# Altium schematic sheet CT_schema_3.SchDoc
size 200 x 173 mm
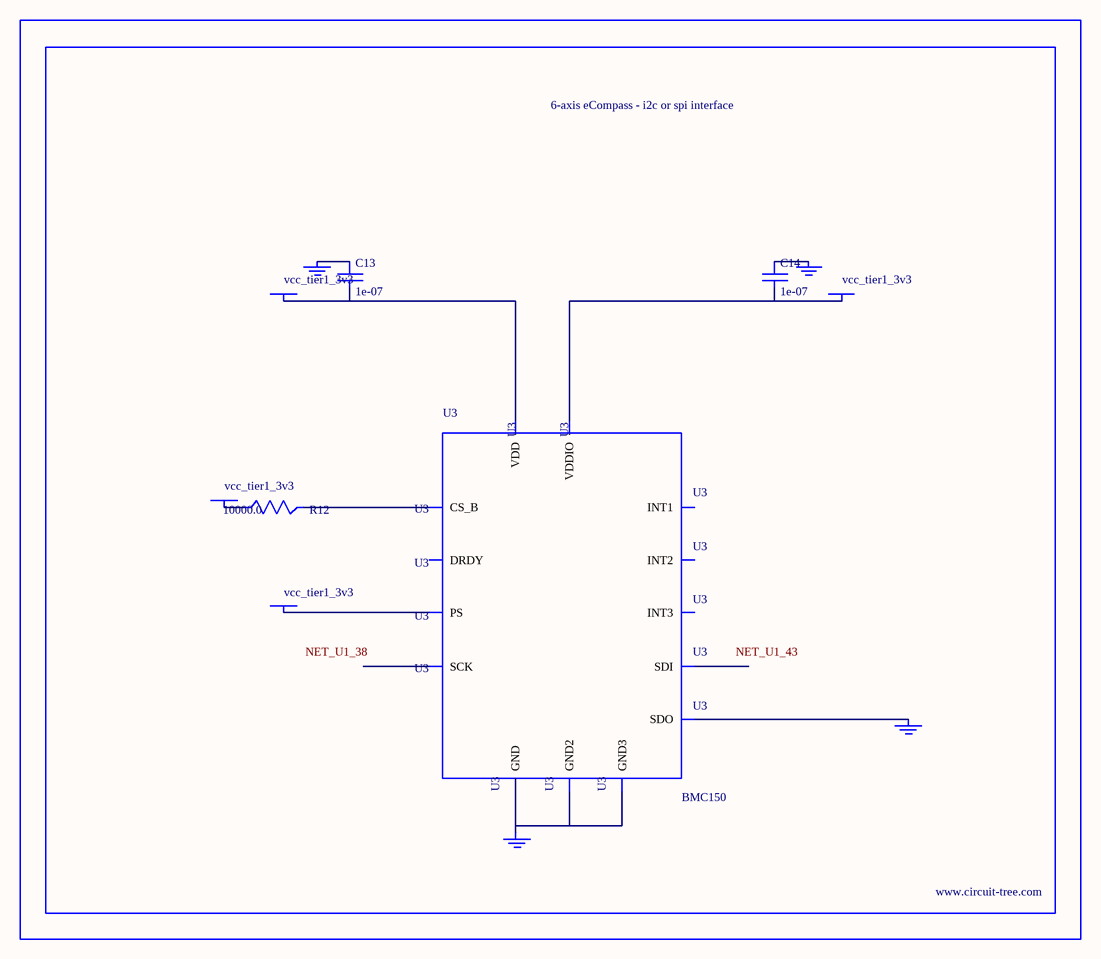
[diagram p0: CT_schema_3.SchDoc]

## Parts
BORDER2  (no value)
C13  1e-07  [C0402]
C14  1e-07  [C0402]
GND_INSTANCE_2_0  (no value)
GND_INSTANCE_2_1  (no value)
GND_INSTANCE_2_2  (no value)
GND_INSTANCE_2_3  (no value)
POWER_INSTANCE_2_0  vcc_tier1_3v3
POWER_INSTANCE_2_1  vcc_tier1_3v3
POWER_INSTANCE_2_2  vcc_tier1_3v3
POWER_INSTANCE_2_3  vcc_tier1_3v3
R12  10000.0  [R0603]
U3  BMC150  [LGA14R35P5X6_200X200X100]

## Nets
NetC13_1: C13.1 GND_INSTANCE_2_1.0(GND)
NetC13_2: C13.2 POWER_INSTANCE_2_0.0(PWR) U3.8(VDD)
NetC14_1: C14.1 GND_INSTANCE_2_2.0(GND)
NetC14_2: C14.2 POWER_INSTANCE_2_1.0(PWR) U3.10(VDDIO)
NetGND_INSTANCE_2_0_0: GND_INSTANCE_2_0.0(GND) U3.1(SDO)
NetGND_INSTANCE_2_3_0: GND_INSTANCE_2_3.0(GND) U3.6(GND) U3.7(GND2) U3.9(GND3)
NetPOWER_INSTANCE_2_2_0: POWER_INSTANCE_2_2.0(PWR) R12.1
NetPOWER_INSTANCE_2_3_0: POWER_INSTANCE_2_3.0(PWR) U3.13(PS)
NetR12_2: R12.2 U3.12(CS_B)

Not connected (* = marked no-connect by the designer): U3 2(INT1) 3(INT2) 4(DRDY) 5(INT3) 11(SCK) 14(SDI)

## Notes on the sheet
- Labels drawn without touching a wire or pin: NET_U1_38, NET_U1_43

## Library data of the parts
BORDER2 = BORDER_PAGE2
C13 C14 = C0402C104K3RACTU
GND_INSTANCE_2_0-GND_INSTANCE_2_3 = GND
POWER_INSTANCE_2_0-POWER_INSTANCE_2_3 = PWR
R12 = RC0603JR-0710KL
